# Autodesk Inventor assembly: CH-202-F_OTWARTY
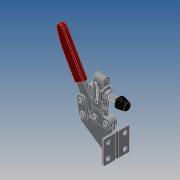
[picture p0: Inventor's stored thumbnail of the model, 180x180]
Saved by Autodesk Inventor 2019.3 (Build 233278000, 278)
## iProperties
Company: Î¢ÈíÖÐ¹ú
Created: 2012-09
Part Number: CH-202-F_OTWARTY
Material: Ogólny
Description: STEP AP203
Document SubType Name: Assembly
Designer: CADENGINEERING4
Sending System: SolidWorks 2010
Preprocessor: SwSTEP 2.0
Title: CH-202-F.STEP
Author: Î¢ÈíÓÃ»§
Revision Number: ÈÎºÎ
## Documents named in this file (9)
- E:\STRONA\Horizontal toggle clamp\CH-202-F\CH-202-F_OTWARTY.iam
- E:\STRONA\Horizontal toggle clamp\CH-202-F\56212-02.ipt
- E:\STRONA\Horizontal toggle clamp\CH-202-F\56212.ipt
- E:\STRONA\Horizontal toggle clamp\CH-202-F\225-D-06.ipt
- E:\STRONA\Horizontal toggle clamp\CH-202-F\202-F-02.ipt
- E:\STRONA\Horizontal toggle clamp\CH-202-F\03.iam
- E:\STRONA\Horizontal toggle clamp\CH-202-F\202-F-01.ipt
- E:\STRONA\Horizontal toggle clamp\CH-202-F\FW516.ipt
- E:\STRONA\Horizontal toggle clamp\CH-202-F\203-F-04.ipt
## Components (14 placed, 14 different names)
1. 56212-02_1 — Zestawiające:5, Zestawiające:7
2. 56212_2 — Równoległe:3, Zestawiające:1, Zestawiające:2, Zestawiające:3, Zestawiające:4, Zestawiające:5
3. 225-D-06_3 — Zestawiające:14, Zestawiające:15
4. 202-F-02_4 — Równoległe:1, Zestawiające:1, Zestawiające:8, Zestawiające:9, Zestawiające:22, Zestawiające:23, Zestawiające:24, Zestawiające:25, Zestawiające:26, Zestawiające:27
5. 03_5 [sub-assembly] — Zestawiające:17, Zestawiające:18, Zestawiające:21, Zestawiające:26, Przejściowe:1
6. 202-F-01_6 — Zestawiające:10, Zestawiające:11, Zestawiające:12, Zestawiające:13, Zestawiające:14, Zestawiające:22, Zestawiające:23, Przejściowe:1
7. FW516_8 — Równoległe:2, Zestawiające:4, Zestawiające:7, Zestawiające:9
8. 203-F-04_9 — Zestawiające:11, Zestawiające:13, Zestawiające:16
9. 56212-02_10 — Równoległe:3, Zestawiające:2, Zestawiające:6
10. 225-D-06_11 — Zestawiające:19, Zestawiające:20
11. 225-D-06_12 — Zestawiające:24, Zestawiające:25
12. 203-F-04_13 — Zestawiające:10, Zestawiające:12, Zestawiające:15, Zestawiające:16, Zestawiające:17, Zestawiające:18, Zestawiające:19, Zestawiające:20
13. 225-D-06_14 — Zestawiające:21, Zestawiające:27
14. FW516_15 — Równoległe:1, Równoległe:2, Zestawiające:3, Zestawiające:6, Zestawiające:8
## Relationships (31: Mate 27, Flush 3, Transitional 1)
- Równoległe:1 [Flush]: 202-F-02_4 ↔ FW516_15
- Równoległe:2 [Flush]: FW516_8 ↔ FW516_15
- Równoległe:3 [Flush]: 56212_2 ↔ 56212-02_10
- Zestawiające:1 [Mate]: 56212_2 ↔ 202-F-02_4
- Zestawiające:2 [Mate]: 56212_2 ↔ 56212-02_10
- Zestawiające:3 [Mate]: 56212_2 ↔ FW516_15
- Zestawiające:4 [Mate]: 56212_2 ↔ FW516_8
- Zestawiające:5 [Mate]: 56212-02_1 ↔ 56212_2
- Zestawiające:6 [Mate]: 56212-02_10 ↔ FW516_15
- Zestawiające:7 [Mate]: 56212-02_1 ↔ FW516_8
- Zestawiające:8 [Mate]: 202-F-02_4 ↔ FW516_15
- Zestawiające:9 [Mate]: 202-F-02_4 ↔ FW516_8
- Zestawiające:10 [Mate]: 202-F-01_6 ↔ 203-F-04_13
- Zestawiające:11 [Mate]: 202-F-01_6 ↔ 203-F-04_9
- Zestawiające:12 [Mate]: 202-F-01_6 ↔ 203-F-04_13
- Zestawiające:13 [Mate]: 202-F-01_6 ↔ 203-F-04_9
- Zestawiające:14 [Mate]: 225-D-06_3 ↔ 202-F-01_6
- Zestawiające:15 [Mate]: 225-D-06_3 ↔ 203-F-04_13
- Zestawiające:16 [Mate]: 203-F-04_9 ↔ 203-F-04_13
- Zestawiające:17 [Mate]: 03_5 ↔ 203-F-04_13
- Zestawiające:18 [Mate]: 03_5 ↔ 203-F-04_13
- Zestawiające:19 [Mate]: 225-D-06_11 ↔ 203-F-04_13
- Zestawiające:20 [Mate]: 225-D-06_11 ↔ 203-F-04_13
- Zestawiające:21 [Mate]: 03_5 ↔ 225-D-06_14
- Zestawiające:22 [Mate]: 202-F-02_4 ↔ 202-F-01_6
- Zestawiające:23 [Mate]: 202-F-02_4 ↔ 202-F-01_6
- Zestawiające:24 [Mate]: 202-F-02_4 ↔ 225-D-06_12
- Zestawiające:25 [Mate]: 202-F-02_4 ↔ 225-D-06_12
- Zestawiające:26 [Mate]: 202-F-02_4 ↔ 03_5
- Zestawiające:27 [Mate]: 202-F-02_4 ↔ 225-D-06_14
- Przejściowe:1 [Transitional]: 03_5 ↔ 202-F-01_6
